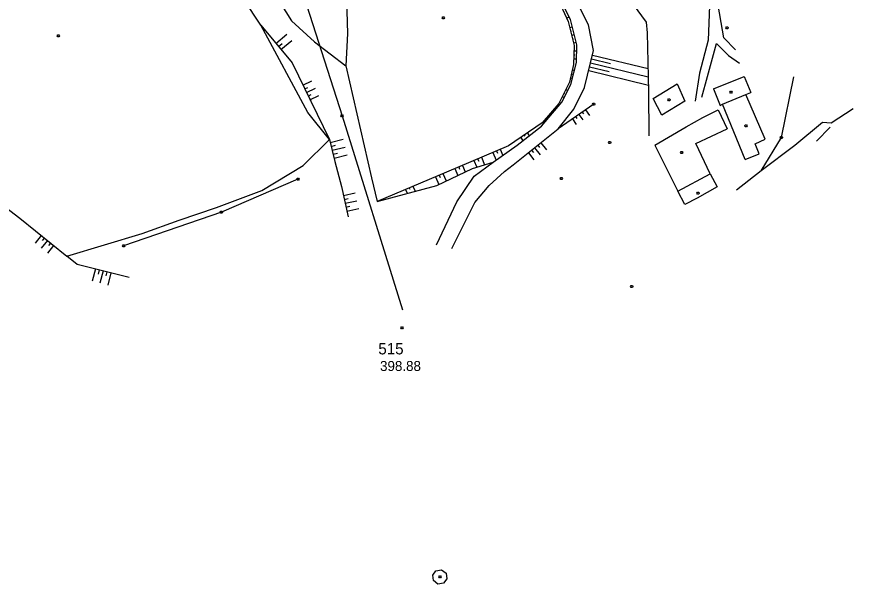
# Model space of a CAD drawing. Extents: x -664960 to -662754, y -993849 to -991145.
# Drawn here: x -663833.4 to -663582.4, y -993848.7 to -993678.4 of the extents above; entities that cross this region are included whole.
import ezdxf

# ---------------------------------------------------------------- set-up
doc = ezdxf.new("R2010")
doc.units = 0
for name, color, linetype in [('Vrstva 1', 7, 'Continuous'), ('Vrstva 11', 7, 'Continuous'), ('Vrstva 12', 7, 'Continuous'), ('Vrstva 13', 7, 'Continuous'), ('Vrstva 18', 7, 'Continuous'), ('Vrstva 21', 7, 'Continuous'), ('Vrstva 23', 7, 'Continuous'), ('Vrstva 27', 7, 'Continuous'), ('Vrstva 33', 7, 'Continuous'), ('Vrstva 37', 7, 'Continuous'), ('Vrstva 57', 7, 'Continuous'), ('Vrstva 63', 7, 'Continuous'), ('Vrstva 8', 7, 'Continuous'), ('Vrstva 9', 7, 'Continuous')]:
    doc.layers.add(name, color=color, linetype=linetype)

msp = doc.modelspace()

# ---------------------------------------------------------------- linework, layer by layer
at = {"layer": 'Vrstva 11'}
for p, q in [((-663624.284, -993700.013), (-663615.08, -993696.325)), ((-663615.08, -993696.325), (-663615.08, -993696.325)), ((-663615.08, -993696.325), (-663613.107, -993701.138)), ((-663621.609, -993704.659), (-663614.632, -993701.711)), ((-663622.91, -993706.31), (-663620.242, -993712.023)), ((-663614.791, -993721.193), (-663621.609, -993704.659)), ((-663589.247, -993711.506), (-663593.345, -993715.768)), ((-663629.599, -993716.392), (-663620.242, -993712.023)), ((-663625.344, -993725.505), (-663629.599, -993716.392))]:
    msp.add_line(p, q, dxfattribs=at)
for points in [[(-663624.284, -993700.013), (-663622.28, -993704.992), (-663621.609, -993704.659)], [(-663614.791, -993721.193), (-663610.628, -993719.492), (-663611.813, -993716.505), (-663608.777, -993715.14), (-663614.632, -993701.711), (-663613.107, -993701.138)], [(-663641.91, -993716.95), (-663632.483, -993711.479), (-663627.54, -993708.61), (-663622.91, -993706.31)], [(-663641.91, -993716.95), (-663634.966, -993730.787), (-663625.344, -993725.505)]]:
    msp.add_lwpolyline(points, dxfattribs=at)
at = {"layer": 'Vrstva 12'}
msp.add_line((-663625.344, -993725.505), (-663623.194, -993729.4), dxfattribs=at)
for points in [[(-663582.357, -993706), (-663588.976, -993710.316), (-663591.576, -993710.097), (-663599.878, -993717.031), (-663609.995, -993724.668), (-663617.427, -993730.427)], [(-663623.194, -993729.4), (-663629.234, -993732.841), (-663632.883, -993734.697), (-663634.966, -993730.787)]]:
    msp.add_lwpolyline(points, dxfattribs=at)
at = {"layer": 'Vrstva 13'}
for points in [[(-663705.201, -993678.415), (-663705.021, -993678.715), (-663705.201, -993679.015), (-663705.561, -993679.015), (-663705.741, -993678.715), (-663705.561, -993678.415), (-663705.201, -993678.415)], [(-663820.764, -993683.838), (-663820.584, -993684.138), (-663820.764, -993684.438), (-663821.124, -993684.438), (-663821.304, -993684.138), (-663821.124, -993683.838), (-663820.764, -993683.838)], [(-663655.265, -993715.797), (-663655.085, -993716.097), (-663655.265, -993716.397), (-663655.625, -993716.397), (-663655.805, -993716.097), (-663655.625, -993715.797), (-663655.265, -993715.797)], [(-663628.754, -993731.023), (-663628.574, -993731.323), (-663628.754, -993731.623), (-663629.114, -993731.623), (-663629.294, -993731.323), (-663629.114, -993731.023), (-663628.754, -993731.023)]]:
    msp.add_lwpolyline(points, dxfattribs=at)
at = {"layer": 'Vrstva 18'}
for points in [[(-663669.8, -993726.61), (-663669.62, -993726.91), (-663669.8, -993727.21), (-663670.16, -993727.21), (-663670.34, -993726.91), (-663670.16, -993726.61), (-663669.8, -993726.61)], [(-663648.663, -993759.052), (-663648.483, -993759.352), (-663648.663, -993759.652), (-663649.023, -993759.652), (-663649.203, -993759.352), (-663649.023, -993759.052), (-663648.663, -993759.052)]]:
    msp.add_lwpolyline(points, dxfattribs=at)
at = {"layer": 'Vrstva 21'}
for points in [[(-663642.447, -993702.908), (-663635.257, -993698.524), (-663632.932, -993703.722), (-663639.819, -993707.928), (-663642.447, -993702.908)], [(-663707.085, -993848.719), (-663708.332, -993847.62), (-663708.56, -993845.977), (-663707.605, -993844.708), (-663705.991, -993844.413), (-663704.594, -993845.409)], [(-663704.594, -993845.409), (-663704.372, -993847.057), (-663705.321, -993848.356), (-663707.085, -993848.719)]]:
    msp.add_lwpolyline(points, dxfattribs=at)
at = {"layer": 'Vrstva 23'}
for points in [[(-663707.41, -993746.81), (-663701.37, -993733.94), (-663696.15, -993726.2), (-663690.45, -993722.08), (-663683.21, -993716.94), (-663675.96, -993711.26), (-663669.86, -993704.06), (-663667.13, -993698.71), (-663665.39, -993692.15), (-663665.33, -993686.82), (-663667.19, -993679.26), (-663670.59, -993672.44)], [(-663702.83, -993747.97), (-663695.93, -993734.17), (-663691.6, -993729.04), (-663687.01, -993724.87), (-663684.4, -993722.84), (-663670.91, -993712.01), (-663666.22, -993706.13), (-663663.01, -993699.67), (-663660.32, -993688.56), (-663661.79, -993680.84), (-663666.37, -993671.83)]]:
    msp.add_lwpolyline(points, dxfattribs=at)
at = {"layer": 'Vrstva 27'}
for points in [[(-663617.75, -993688.33), (-663621.2, -993684.71), (-663623.27, -993672.48), (-663626.03, -993651.59), (-663631.7, -993630.02), (-663637.5, -993620.58), (-663645.57, -993611.43), (-663656.3, -993604.85), (-663664.96, -993599.76), (-663673.95, -993591.13), (-663682.59, -993580.63), (-663689.69, -993567.67), (-663695.94, -993548.39), (-663706.15, -993526.98), (-663713.97, -993515.23), (-663721.34, -993504.19), (-663723.25, -993495.81), (-663719.71, -993485.94), (-663719.1, -993478.49)], [(-663727.12, -993491.86), (-663723.61, -993505.05), (-663715.54, -993517), (-663708.61, -993527.89), (-663698.31, -993549.18), (-663692.46, -993567.57), (-663684.5, -993582.39), (-663676.76, -993593.09), (-663666.63, -993601.82), (-663657.5, -993607.21), (-663648.73, -993613.27), (-663639.9, -993622.05), (-663634.08, -993630.75), (-663628.07, -993651.96), (-663625.42, -993672.38), (-663625.87, -993685.44), (-663628.47, -993695.31), (-663629.86, -993703.76)], [(-663627.8, -993702.57), (-663626.07, -993696.32), (-663623.42, -993686.45), (-663619.79, -993690.03), (-663616.51, -993692.33)]]:
    msp.add_lwpolyline(points, dxfattribs=at)
at = {"layer": 'Vrstva 33'}
msp.add_lwpolyline([(-663660.07, -993704.28), (-663659.89, -993704.58), (-663660.07, -993704.88), (-663660.43, -993704.88), (-663660.61, -993704.58), (-663660.43, -993704.28), (-663660.07, -993704.28)], dxfattribs=at)
at = {"layer": 'Vrstva 37'}
msp.add_lwpolyline([(-663735.62, -993707.85), (-663735.44, -993708.15), (-663735.62, -993708.45), (-663735.98, -993708.45), (-663736.16, -993708.15), (-663735.98, -993707.85), (-663735.62, -993707.85)], dxfattribs=at)
at = {"layer": 'Vrstva 57'}
for points in [[(-663937.17, -993067.28), (-663921.25, -993118.58), (-663905.79, -993167.82), (-663887.66, -993226.85), (-663873.48, -993270.98), (-663861.55, -993308.04), (-663843.55, -993366.56), (-663828.28, -993415.08), (-663809.04, -993475.6), (-663791.79, -993531.02), (-663772.5, -993592.28), (-663754.33, -993650.13), (-663735.8, -993708.15), (-663717.65, -993766.39)], [(-663603.731, -993714.37), (-663603.551, -993714.67), (-663603.731, -993714.97), (-663604.091, -993714.97), (-663604.271, -993714.67), (-663604.091, -993714.37), (-663603.731, -993714.37)]]:
    msp.add_lwpolyline(points, dxfattribs=at)
at = {"layer": 'Vrstva 63'}
for p, q in [((-663668.388, -993678.808), (-663667.596, -993678.447)), ((-663667.483, -993681.579), (-663666.671, -993681.371)), ((-663755.68, -993686.375), (-663752.393, -993683.655)), ((-663667.187, -993682.742), (-663666.919, -993682.673)), ((-663666.89, -993683.904), (-663666.097, -993683.702)), ((-663754.915, -993687.299), (-663753.821, -993686.394)), ((-663754.151, -993688.224), (-663750.863, -993685.504)), ((-663666.593, -993685.067), (-663666.333, -993685.001)), ((-663666.297, -993686.23), (-663665.524, -993686.033)), ((-663666.153, -993688.603), (-663665.35, -993688.629)), ((-663666.232, -993691.002), (-663665.377, -993691.03)), ((-663666.192, -993689.802), (-663665.917, -993689.811)), ((-663660.928, -993691.069), (-663655.269, -993692.439)), ((-663660.645, -993689.903), (-663643.963, -993693.942)), ((-663666.677, -993694.365), (-663666.02, -993694.524)), ((-663661.492, -993693.402), (-663655.628, -993694.822)), ((-663661.21, -993692.236), (-663643.908, -993696.425)), ((-663667.24, -993696.698), (-663666.635, -993696.844)), ((-663666.959, -993695.531), (-663666.749, -993695.582)), ((-663661.775, -993694.568), (-663643.853, -993698.908)), ((-663747.534, -993698.971), (-663744.867, -993697.667)), ((-663747.007, -993700.049), (-663746.119, -993699.615)), ((-663746.48, -993701.127), (-663743.813, -993699.823)), ((-663745.953, -993702.205), (-663745.065, -993701.771)), ((-663669.189, -993701.3), (-663668.993, -993701.397)), ((-663668.658, -993700.224), (-663668.055, -993700.522)), ((-663745.426, -993703.283), (-663742.759, -993701.979)), ((-663669.72, -993702.376), (-663669.145, -993702.66)), ((-663672.432, -993706.409), (-663672.094, -993706.696)), ((-663660.25, -993704.58), (-663670.91, -993712.01)), ((-663662.731, -993706.309), (-663661.551, -993708.002)), ((-663673.985, -993708.239), (-663673.645, -993708.528)), ((-663673.208, -993707.324), (-663673.096, -993707.42)), ((-663666.669, -993709.054), (-663665.489, -993710.747)), ((-663665.684, -993708.368), (-663665.291, -993708.931)), ((-663664.7, -993707.682), (-663663.52, -993709.374)), ((-663663.715, -993706.995), (-663663.322, -993707.559)), ((-663681.181, -993713.964), (-663680.977, -993714.266)), ((-663680.186, -993713.292), (-663679.621, -993714.128)), ((-663739.36, -993716.128), (-663735.433, -993715.157)), ((-663739.072, -993717.293), (-663737.764, -993716.97)), ((-663682.175, -993714.636), (-663681.515, -993715.612)), ((-663677.076, -993716.96), (-663676.513, -993717.661)), ((-663676.14, -993716.209), (-663674.45, -993718.313)), ((-663738.784, -993718.458), (-663734.857, -993717.487)), ((-663738.496, -993719.623), (-663737.188, -993719.3)), ((-663690.504, -993719.098), (-663689.52, -993721.42)), ((-663689.398, -993718.63), (-663689.105, -993719.322)), ((-663688.293, -993718.162), (-663687.516, -993719.997)), ((-663679.883, -993719.213), (-663678.193, -993721.318)), ((-663678.947, -993718.462), (-663678.384, -993719.163)), ((-663678.011, -993717.711), (-663676.321, -993719.816)), ((-663738.208, -993720.788), (-663734.28, -993719.817)), ((-663696.202, -993721.51), (-663695.337, -993723.553)), ((-663695.096, -993721.042), (-663694.792, -993721.762)), ((-663693.991, -993720.574), (-663693.025, -993722.856)), ((-663701.9, -993723.923), (-663701.015, -993726.011)), ((-663700.794, -993723.455), (-663700.506, -993724.136)), ((-663699.689, -993722.987), (-663698.843, -993724.987)), ((-663707.727, -993726.39), (-663706.745, -993728.71)), ((-663706.622, -993725.922), (-663706.301, -993726.68)), ((-663705.517, -993725.455), (-663704.572, -993727.686)), ((-663714.531, -993729.271), (-663713.901, -993730.758)), ((-663735.386, -993732.03), (-663731.829, -993731.256)), ((-663716.741, -993730.207), (-663716.24, -993731.388)), ((-663715.636, -993729.739), (-663715.447, -993730.183)), ((-663735.131, -993733.202), (-663733.946, -993732.945)), ((-663734.876, -993734.375), (-663731.319, -993733.601)), ((-663734.621, -993735.547), (-663733.436, -993735.29)), ((-663734.366, -993736.72), (-663730.808, -993735.946)), ((-663826.089, -993744.032), (-663827.955, -993746.32)), ((-663824.229, -993745.549), (-663826.095, -993747.837)), ((-663825.159, -993744.791), (-663825.78, -993745.552)), ((-663822.369, -993747.066), (-663824.236, -993749.354)), ((-663823.299, -993746.308), (-663823.921, -993747.07)), ((-663809.847, -993754.092), (-663810.779, -993757.749)), ((-663808.685, -993754.388), (-663808.995, -993755.606)), ((-663807.522, -993754.684), (-663808.454, -993758.341)), ((-663806.359, -993754.981), (-663806.669, -993756.198)), ((-663805.196, -993755.277), (-663806.128, -993758.934))]:
    msp.add_line(p, q, dxfattribs=at)
for points in [[(-663803.15, -993571.01), (-663804.29, -993562.17), (-663800.94, -993563.03), (-663799.25, -993564.54), (-663794.89, -993583.79), (-663788.98, -993595.19), (-663785.24, -993605.81), (-663778.53, -993625.58), (-663772.44, -993642.86), (-663766.79, -993651.48), (-663757.75, -993668.75), (-663750.98, -993679.59), (-663744.11, -993685.89), (-663734.62, -993693.1), (-663726.91, -993726.75), (-663725.289, -993733.826)], [(-663848.97, -993726.38), (-663832.49, -993738.81), (-663818.43, -993750.28), (-663795.81, -993743.41), (-663784.7, -993739.47), (-663773.5, -993735.67), (-663759.91, -993730.52), (-663747.43, -993723.08), (-663739.58, -993715.24), (-663746.06, -993707.14), (-663760.16, -993680.96), (-663780.55, -993649.96), (-663783.63, -993642.31), (-663791.33, -993613.67), (-663797.54, -993590.48), (-663803.15, -993571.01)], [(-663666.63, -993601.82), (-663663.33, -993612.32), (-663661.37, -993640.08), (-663658.98, -993647.89), (-663657.39, -993656.74), (-663648.46, -993674.7), (-663644.5, -993680.06), (-663644.2, -993683.26), (-663643.81, -993700.84), (-663643.71, -993714.16)], [(-663686.67, -993641.66), (-663681.48, -993653.41), (-663671.26, -993672.51), (-663667.94, -993679.79), (-663666.1, -993687), (-663666.29, -993692.76), (-663667.55, -993697.98), (-663670.71, -993704.38), (-663675.7, -993710.26), (-663685.88, -993717.14), (-663704.42, -993724.99), (-663725.289, -993733.826)], [(-663734.79, -993663.07), (-663734.14, -993683.4), (-663734.62, -993693.1)], [(-663760.16, -993680.96), (-663750.82, -993692.25), (-663739.58, -993715.24)], [(-663620.05, -993681.46), (-663619.87, -993681.76), (-663620.05, -993682.06), (-663620.41, -993682.06), (-663620.59, -993681.76), (-663620.41, -993681.46), (-663620.05, -993681.46)], [(-663609.995, -993724.668), (-663603.911, -993714.67), (-663600.202, -993696.412)], [(-663739.58, -993715.24), (-663737.95, -993721.83), (-663735.98, -993729.3), (-663734, -993738.4)], [(-663725.289, -993733.826), (-663707.34, -993728.99), (-663696.62, -993723.94), (-663690.45, -993722.08)], [(-663748.88, -993726.79), (-663748.7, -993727.09), (-663748.88, -993727.39), (-663749.24, -993727.39), (-663749.42, -993727.09), (-663749.24, -993726.79), (-663748.88, -993726.79)], [(-663749.06, -993727.09), (-663772.01, -993737.08), (-663801.35, -993747.1)], [(-663771.83, -993736.78), (-663771.65, -993737.08), (-663771.83, -993737.38), (-663772.19, -993737.38), (-663772.37, -993737.08), (-663772.19, -993736.78), (-663771.83, -993736.78)], [(-663801.17, -993746.8), (-663800.99, -993747.1), (-663801.17, -993747.4), (-663801.53, -993747.4), (-663801.71, -993747.1), (-663801.53, -993746.8), (-663801.17, -993746.8)], [(-663799.73, -993756.67), (-663815.27, -993752.71), (-663818.43, -993750.28)]]:
    msp.add_lwpolyline(points, dxfattribs=at)
at = {"layer": 'Vrstva 8'}
msp.add_lwpolyline([(-663717.61, -993771.49), (-663717.43, -993771.79), (-663717.61, -993772.09), (-663717.97, -993772.09), (-663718.15, -993771.79), (-663717.97, -993771.49), (-663717.61, -993771.49)], dxfattribs=at)
at = {"layer": 'Vrstva 9'}
for points in [[(-663618.886, -993700.683), (-663618.706, -993700.983), (-663618.886, -993701.283), (-663619.246, -993701.283), (-663619.426, -993700.983), (-663619.246, -993700.683), (-663618.886, -993700.683)], [(-663637.458, -993702.996), (-663637.278, -993703.296), (-663637.458, -993703.596), (-663637.818, -993703.596), (-663637.998, -993703.296), (-663637.818, -993702.996), (-663637.458, -993702.996)], [(-663614.397, -993710.819), (-663614.217, -993711.119), (-663614.397, -993711.419), (-663614.757, -993711.419), (-663614.937, -993711.119), (-663614.757, -993710.819), (-663614.397, -993710.819)], [(-663633.695, -993718.826), (-663633.515, -993719.126), (-663633.695, -993719.426), (-663634.055, -993719.426), (-663634.235, -993719.126), (-663634.055, -993718.826), (-663633.695, -993718.826)], [(-663706.207, -993846.226), (-663706.027, -993846.526), (-663706.207, -993846.826), (-663706.567, -993846.826), (-663706.747, -993846.526), (-663706.567, -993846.226), (-663706.207, -993846.226)]]:
    msp.add_lwpolyline(points, dxfattribs=at)

# ---------------------------------------------------------------- texts
at = {"layer": 'Vrstva 1'}
msp.add_text('515', height=3.4, dxfattribs=at).set_placement((-663724.916, -993779.728))
at = {"layer": 'Vrstva 63'}
msp.add_text('398.88', height=3, dxfattribs=at).set_placement((-663724.392, -993784.708))

doc.saveas('drawing.dxf')
